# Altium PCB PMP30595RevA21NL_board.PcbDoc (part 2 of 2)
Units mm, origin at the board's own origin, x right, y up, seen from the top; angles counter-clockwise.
Board outline 110.49 x 76.2 mm, 2 copper layers (Top Layer, Bottom Layer), stack 1.575 mm thick; 77 components, 38 nets, 187 pads, 95 vias.
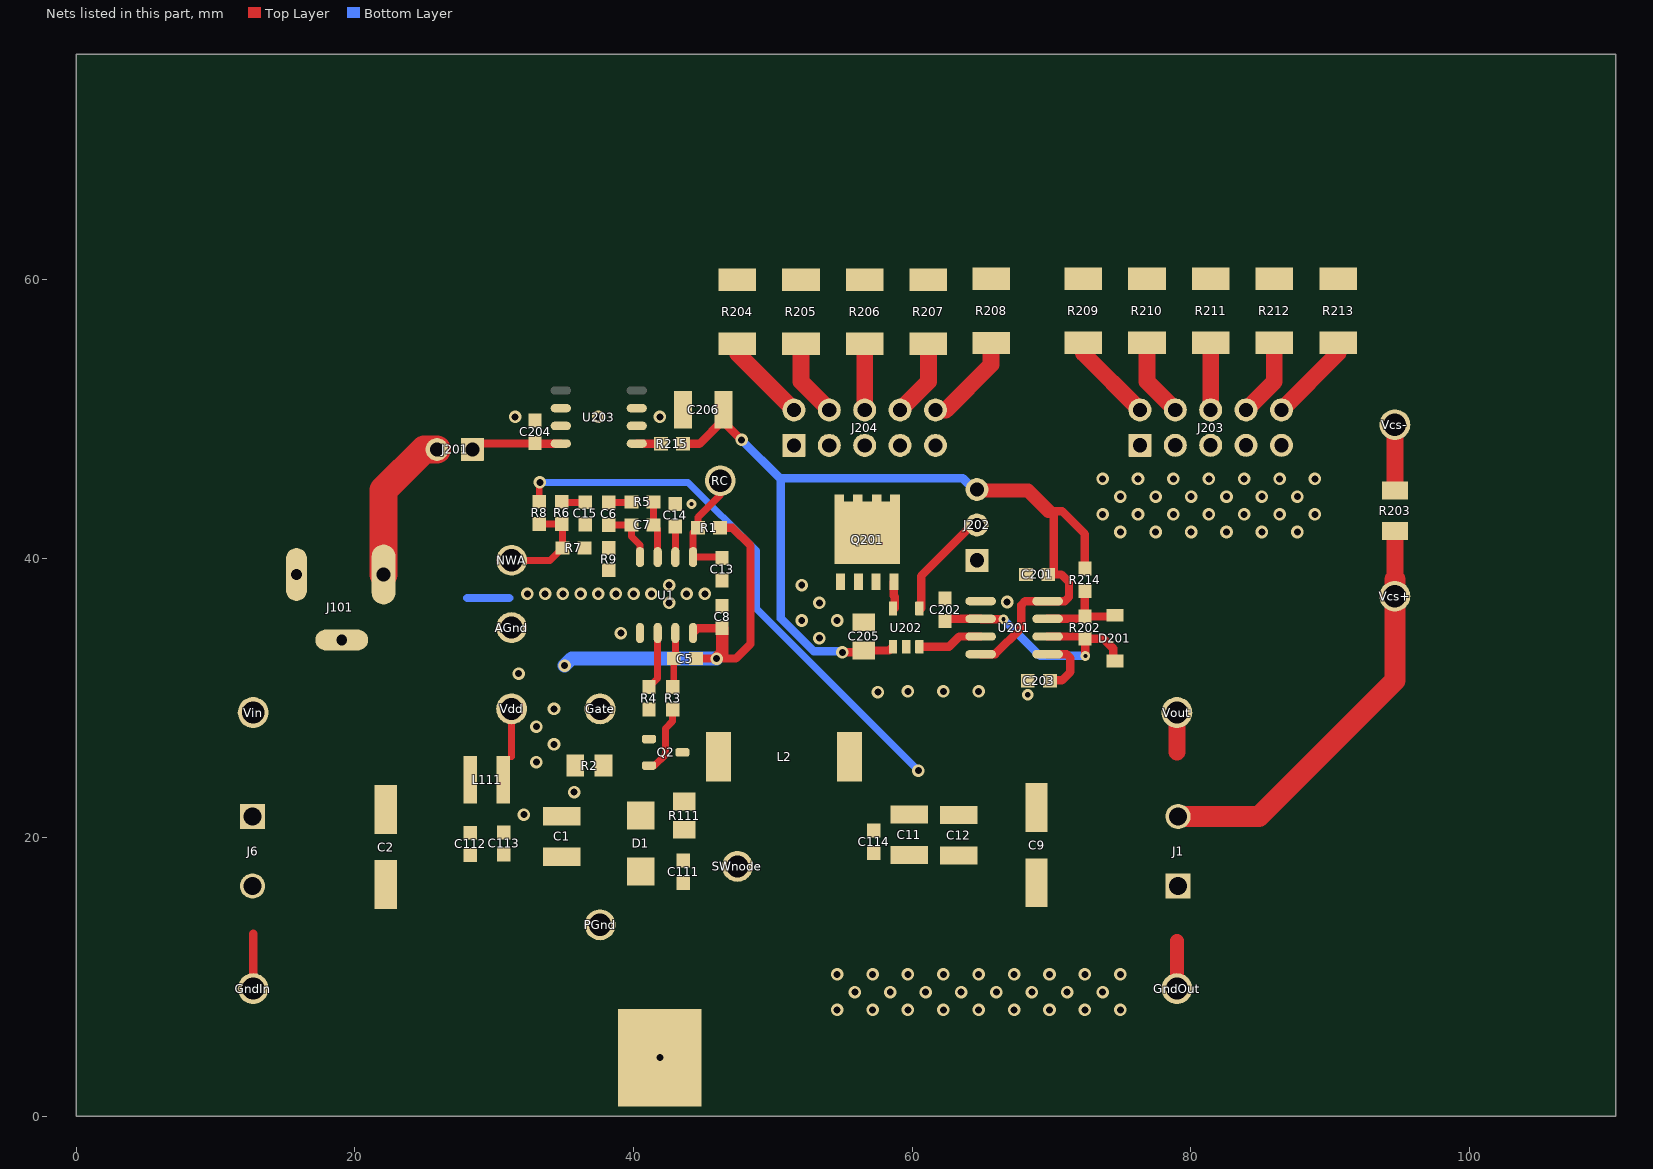
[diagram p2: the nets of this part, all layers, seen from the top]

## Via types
v1: diameter 0.9, hole 0.5, Top Layer to Bottom Layer, 81 vias
v2: diameter 0.9, hole 0.5, Top Layer to Bottom Layer, tented top, 10 vias
v3: diameter 0.7, hole 0.3, Top Layer to Bottom Layer, 2 vias
v4: diameter 0.7, hole 0.3, Top Layer to Bottom Layer, tented top, 1 vias
v5: diameter 0.8, hole 0.4, Top Layer to Bottom Layer, tented top, 1 vias

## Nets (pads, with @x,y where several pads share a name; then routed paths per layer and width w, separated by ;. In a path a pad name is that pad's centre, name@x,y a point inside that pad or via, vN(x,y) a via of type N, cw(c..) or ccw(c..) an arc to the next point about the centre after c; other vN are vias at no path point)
5V0: C9.1 C11.1 C12.1 C114.1 J1.2 L2.2 R8.1 R203.1 Vcs+.1 Vout.1 | length 73.9
  Top Layer w0.5: R8.1@33.232,44.08 33.232,45.417 v1(33.282,45.466)
  Top Layer w1.2: 78.994,26.096 Vout.1@78.994,28.956 ; Vcs+.1@94.635,37.302 R203.1@94.635,41.984
  Top Layer w1.5: J1.2@79.079,21.502 84.875,21.502 94.635,31.262 94.635,38.492
  Bottom Layer w0.5: v1(33.282,45.466) 43.92,45.466 48.813,40.573 48.813,36.404 v1(60.439,24.778)
12V0: C2.1 C112.1 J6.1 J101.1 J201.2 L111.1 Vin.1 | length 11.1
  Top Layer w2: J101.1@22.056,38.862 22.056,44.916 24.975,47.835 J201.2@25.894,47.835
GND: AGnd.1 C1.2 C2.2 C8.2 C9.2 C11.2 C12.2 C13.2 C14.2 C111.2 C112.2 C113.2 C114.2 C201.2 C202.2 C203.2 C204.2 C205.2 C206.2 D1.2 GndIn.1 GndOut.1 J1.1 J6.2 J101.2 J101.3 J202.1 J203.1 J203.3 J203.5 J203.7 J203.9 pad.1 PGnd.1 Q201.1 Q201.2 Q201.3 R9.1 U1.5 U201.1 U202.2 U203.2 U203.3 U203.6 U203.7 | length 10.4
  Top Layer w0.6: GndIn.1@12.7,9.144 12.7,13.081
  Top Layer w1: GndOut.1@78.994,9.144 78.994,12.573
  Bottom Layer w0.6: 28.067,37.172 31.076,37.172
  other v1: 54.61,7.62 57.15,7.62 59.69,7.62 62.23,7.62 64.77,7.62 67.31,7.62 69.85,7.62 72.39,7.62 74.93,7.62 55.88,8.89 58.42,8.89 60.96,8.89 63.5,8.89 66.04,8.89 68.58,8.89 71.12,8.89 73.66,8.89 54.61,10.16 57.15,10.16 59.69,10.16 62.23,10.16 64.77,10.16 67.31,10.16 69.85,10.16 72.39,10.16 74.93,10.16 57.531,30.42 59.69,30.48 62.23,30.48 64.77,30.48 53.34,34.29 39.09,34.66 52.07,35.56 54.61,35.56 53.34,36.83 32.385,37.465 33.655,37.465 34.925,37.465 36.195,37.465 37.465,37.465 38.735,37.465 52.07,38.1 74.93,41.91 77.47,41.91 80.01,41.91 82.55,41.91 85.09,41.91 87.63,41.91 73.66,43.18 76.2,43.18 78.74,43.18 81.28,43.18 83.82,43.18 86.36,43.18 88.9,43.18 74.93,44.45 77.47,44.45 80.01,44.45 82.55,44.45 85.09,44.45 87.63,44.45 73.66,45.72 76.2,45.72 78.74,45.72 81.28,45.72 83.82,45.72 86.36,45.72 88.9,45.72 31.496,50.165 37.465,50.165 41.893,50.165
  other v2: 42.545,36.83 66.802,36.885 40.005,37.465 41.275,37.465 43.815,37.465 45.113,37.465 42.545,38.1
  other v3: 44.159,43.916
  other v5: 68.288,30.226
NetC1_1: C1.1 C5.1 C8.1 C113.1 L111.2 R1.2 R2.1 U1.8 Vdd.1 | length 33.5
  Top Layer w0.5: 31.242,25.781 Vdd.1@31.242,29.21 ; C5.1@44.268,33.043 C5.1@44.484,32.827
  Top Layer w0.6: U1.8@44.268,34.66 44.622,35.014 C8.1@46.355,35.014 ; C5.1@44.484,32.827 v2(45.959,32.827) 47.337,32.827 48.387,33.877 48.387,40.927 47.103,42.211 R1.2@46.211,42.211
  Top Layer w0.9: v2(45.959,32.827) 46.355,33.223 C8.1@46.355,35.014
  Bottom Layer w1: v1(35.052,32.317) 35.562,32.827 v2(45.959,32.827)
  other v1: 32.131,21.625 35.73,23.247 33.02,25.4 34.29,26.67 33.02,27.94 34.29,29.21 31.75,31.75
NetC5_2: C5.2 R3.1 U1.7 | length 4
  Top Layer w0.5: R3.1@42.806,30.772 42.884,30.849 C5.2@42.884,32.827 42.998,32.941 U1.7@42.998,34.66
NetC6_1: C6.1 C7.1 C15.2 R7.2 R9.2 U1.4 | length 4.2
  Top Layer w0.5: C6.1@38.227,42.418 C7.1@39.84,42.418 39.84,41.592 40.458,40.973 U1.4@40.458,40.11
NetC6_2: C6.2 R5.2 | length 1.6
  Top Layer w0.5: C6.2@38.227,44.018 39.789,44.018 R5.2@39.84,44.069
NetC7_2: C7.2 R5.1 U1.3 | length 4.1
  Top Layer w0.5: R5.1@41.44,44.069 C7.2@41.44,42.418 41.728,42.13 U1.3@41.728,40.11
NetC13_1: C13.1 R1.1 RC.1 U1.1 | length 8.4
  Top Layer w0.5: RC.1@46.228,45.593 46.228,44.585 44.611,42.968 R1.1@44.611,42.211 44.268,41.868 U1.1@44.268,40.11 46.288,40.11 C13.1@46.355,40.043
NetC14_1: C14.1 U1.2 | length 2.2
  Top Layer w0.5: U1.2@42.998,40.11 C14.1@42.998,42.316
NetC15_1: C15.1 R6.1 | length 1.7
  Top Layer w0.5: R6.1@34.85,44.08 34.887,44.043 C15.1@36.534,44.043
NetC111_1: C111.1 R111.1
NetC201_1: C201.1 C205.1 C206.1 J202.3 R214.2 R215.2 U201.4 U201.8 U202.1 | length 72.3
  Top Layer w0.6: R215.2@43.556,48.235 44.718,48.235 C206.1@46.447,49.964 ; C206.1@46.447,50.673 C206.1@46.447,49.964 ; v2(47.752,48.514) 46.447,49.819 C206.1@46.447,49.964 ; v2(54.991,33.274) 56.388,33.274 C205.1@56.515,33.401 58.337,33.401 U202.1@58.613,33.677 ; U201.4@64.91,33.139 65.948,33.139 67.826,35.017 67.826,36.672 68.103,36.949 U201.8@69.71,36.949 70.949,36.949 71.247,37.247 71.247,38.312 70.697,38.862 C201.1@69.761,38.862 70.157,39.258 70.157,43.021 69.776,43.402 70.744,43.402 72.39,41.755 R214.2@72.39,39.281 ; C201.1@69.776,38.681 C201.1@69.863,38.768
  Top Layer w1: J202.3@64.516,44.873 68.305,44.873 69.776,43.402
  Bottom Layer w0.6: v2(47.752,48.514) 50.501,45.765 ; v2(54.991,33.274) 54.925,33.34 52.938,33.34 50.572,35.706 50.572,45.694 50.501,45.765 ; J202.3@64.516,44.873 63.624,45.765 50.501,45.765
NetC202_1: C202.1 D201.1 R202.1 U201.2 U201.6 | length 18.3
  Top Layer w0.6: C202.1@62.484,35.514 62.649,35.679 U201.2@64.91,35.679 64.943,35.646 v4(66.548,35.646) ; U201.6@69.71,34.409 72.229,34.409 R202.1@72.39,34.248 ; v3(72.423,33.02) 72.423,34.215 R202.1@72.39,34.248 ; D201.1@74.422,32.644 74.422,33.546 73.72,34.248 R202.1@72.39,34.248
  Bottom Layer w0.6: v4(66.548,35.646) 69.174,33.02 v3(72.423,33.02)
NetC203_1: C203.1 U201.5 | length 4.5
  Top Layer w0.6: U201.5@69.71,33.139 71.068,33.139 71.348,32.859 71.348,31.877 70.733,31.262 69.916,31.262 C203.1@69.888,31.234
NetC204_1: C204.1 J201.1 U203.8 | length 6.9
  Top Layer w0.6: J201.1@27.94,48.26 32.881,48.26 C204.1@32.931,48.31 32.987,48.254 U203.8@34.778,48.254
NetD1_1: D1.1 L2.1 Q2.3 R111.2 SWnode.1
NetD201_2: D201.2 R202.2 R214.1 U201.7 | length 6.6
  Top Layer w0.6: U201.7@69.71,35.679 72.221,35.679 R202.2@72.39,35.848 ; R214.1@72.39,37.681 R202.2@72.39,35.848 ; D201.2@74.422,35.919 74.35,35.848 R202.2@72.39,35.848
NetGate_1: Gate.1 Q2.1 R4.2
NetJ202_2: J202.2 U202.4 | length 7.7
  Top Layer w0.6: U202.4@60.64,36.427 60.64,38.742 64.231,42.333 J202.2@64.516,42.333
NetJ203_2: J203.2 R209.1 | length 6.5
  Top Layer w1.2: R209.1@72.27,55.485 72.27,54.737 J203.2@76.334,50.673
NetJ203_4: J203.4 R210.1 | length 5.7
  Top Layer w1.2: R210.1@76.842,55.485 76.842,52.705 J203.4@78.874,50.673
NetJ203_6: J203.6 R211.1 | length 4.8
  Top Layer w1.2: J203.6@81.414,50.673 R211.1@81.414,55.485
NetJ203_8: J203.8 R212.1 | length 5.7
  Top Layer w1.2: J203.8@83.954,50.673 85.986,52.705 R212.1@85.986,55.485
NetJ203_10: J203.10 R213.1 | length 6.5
  Top Layer w1.2: J203.10@86.494,50.673 90.558,54.737 R213.1@90.558,55.485
NetJ204_1: J204.1 J204.3 J204.5 J204.7 J204.9 Q201.5 Q201.6 Q201.7 Q201.8 Q201.9
NetJ204_2: J204.2 R204.1 | length 6.4
  Top Layer w1.2: R204.1@47.442,55.423 47.442,54.731 J204.2@51.506,50.667
NetJ204_4: J204.4 R205.1 | length 5.6
  Top Layer w1.2: R205.1@52.014,55.423 52.014,52.699 J204.4@54.046,50.667
NetJ204_6: J204.6 R206.1 | length 4.8
  Top Layer w1.2: J204.6@56.586,50.667 R206.1@56.586,55.423
NetJ204_8: J204.8 R207.1 | length 5.6
  Top Layer w1.2: J204.8@59.126,50.667 61.158,52.699 R207.1@61.158,55.423
NetJ204_10: J204.10 R208.1 | length 6.9
  Top Layer w1.2: J204.10@61.666,50.667 62.411,50.667 65.656,53.912 R208.1@65.656,55.479
NetNWA_1: NWA.1 R6.2 R7.1 R8.2 | length 7.4
  Top Layer w0.5: NWA.1@31.242,39.878 33.998,39.878 R7.1@34.887,40.767 34.887,42.443 R6.2@34.85,42.48 R8.2@33.232,42.48
NetQ2_2: Q2.2 R2.2 R3.2 | length 5
  Top Layer w0.5: Q2.2@41.106,25.146 41.511,25.146 42.291,25.926 42.291,27.813 42.806,28.328 R3.2@42.806,29.172
NetQ201_4: Q201.4 U202.5 | length 1.9
  Top Layer w0.6: Q201.4@58.674,38.346 58.674,37.338 58.74,37.272 U202.5@58.74,36.427
NetR4_1: R4.1 U1.6 | length 4.1
  Top Layer w0.5: R4.1@41.106,30.772 41.728,31.394 U1.6@41.728,34.66
NetR203_2: R203.2 R204.2 R205.2 R206.2 R207.2 R208.2 R209.2 R210.2 R211.2 R212.2 R213.2 Vcs-.1 | length 4.7
  Top Layer w1.2: R203.2@94.635,44.884 Vcs-.1@94.635,49.61
NetR215_1: R215.1 U203.1 | length 1.7
  Top Layer w0.6: U203.1@40.228,48.254 41.937,48.254 R215.1@41.956,48.235
NetU201_3: U201.3 U202.3 | length 4.4
  Top Layer w0.6: U202.3@60.767,33.677 62.641,33.677 63.373,34.409 U201.3@64.91,34.409
pads on no net: U203.4 U203.5

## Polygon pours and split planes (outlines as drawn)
NetC1_1 on Top Layer "TOP_LAYER_NETC1_1_P055" (solid, remove dead copper, pour order 55): 46.355,33.223 46.355,31.872 46.074,31.591 44.047,31.591 43.861,31.777 43.861,33.191 44.069,33.399 44.073,33.395 46.183,33.395
NetR215_1 on Top Layer "TOP_LAYER_NETR215_1_P051" (solid, remove dead copper, pour order 51): 37.93,48.437 38.203,48.71 42.418,48.71 42.418,47.112 42.164,46.857 38.227,46.863 37.93,47.16
NetC204_1 on Top Layer "TOP_LAYER_NETC204_1_P050" (solid, remove dead copper, pour order 50): 27.432,47.105 27.674,46.863 27.788,46.863 36.676,46.863 36.812,47 36.812,48.444 36.488,48.768 27.432,48.768
5V0 on Top Layer "TOP_LAYER_5V0_P048" (solid, remove dead copper, pour order 48): 79.479,24.13 84.328,24.13 92.837,32.639 92.837,36.667 93.472,37.302 95.816,37.302 96.413,36.705 96.413,30.881 85.675,20.143 79.479,20.143
GND on Top Layer "TOP_LAYER_GND_P040" (solid, remove dead copper, pour order 40): 40.416,51.181 44.028,51.181 44.268,50.941 44.268,49.491 43.888,49.11 43.871,49.127 40.803,49.127 29.946,49.127 29.718,49.355 29.718,50.941 29.958,51.181
GND on Top Layer "TOP_LAYER_GND_P032" (solid, remove dead copper, pour order 32): 50.69,41.744 53.267,39.167 60.677,39.167 63.881,42.371 63.881,47.371 65.786,49.276 88.519,49.276 90.424,47.371 90.424,32.206 87.64,29.422 55.918,29.422 50.69,34.65
NetJ204_1 on Top Layer "TOP_LAYER_NETJ204_1_P030" (solid, remove dead copper, pour order 30): 53.794,39.624 50.673,42.745 50.673,46.863 50.673,49.11 62.266,49.11 62.608,48.768 62.608,41.957 60.275,39.624
no net on Top Layer "TOP_LAYER_NONET_P028" (solid, remove dead copper, pour order 28): 47.879,50.11
NetR203_2 on Top Layer "TOP_LAYER_NETR203_2_P024" (solid, remove dead copper, pour order 24): 43.307,59.69 44.577,58.42 90.805,58.42 92.837,56.388 92.837,48.006 93.345,47.498 96.139,47.498 97.282,48.641 97.282,69.025 94.044,72.263 44.718,72.263 44.397,72.21 43.307,71.12
NetC6_1 on Top Layer "TOP_LAYER_NETC6_1_P022" (solid, remove dead copper, pour order 22): 38.735,40.25 38.735,42.926 35.883,42.926 35.883,40.259
GND on Top Layer "TOP_LAYER_GND_P018" (solid, remove dead copper, pour order 18): 30.217,33.782 30.217,44.314 31.75,45.847 47.394,45.847 48.895,44.346 48.895,33.782
NetC111_1 on Top Layer "TOP_LAYER_NETC111_1_P002" (solid, remove dead copper, pour order 2): 44.484,17.793 44.484,21.209 42.757,21.209 42.757,17.793
5V0 on Top Layer "TOP_LAYER_5V0_P010" (solid, remove dead copper, pour order 10): 54.619,19.939 54.619,28.263 81.534,28.263 81.534,20.066
NetGate_1 on Top Layer "TOP_LAYER_NETGATE_1_P009" (solid, remove dead copper, pour order 9): 38.532,26.543 cw(c38.532,29.083) 35.992,29.083 35.992,29.213 cw(c37.551,29.213) 37.551,30.772 38.778,30.772 cw(c38.778,30.146) 39.22,30.589 39.71,30.099 ccw(c40.323,30.712) 40.323,29.845 41.474,29.845 cw(c41.474,29.591) 41.728,29.591 41.728,26.869 cw(c41.402,26.869) 41.402,26.543
NetD1_1 on Top Layer "TOP_LAYER_NETD1_1_P000" (solid, remove dead copper, pour order 0): 48.641,17.925 cw(c47.442,17.925) 47.442,16.726 cw(c47.442,17.94) 46.228,17.94 46.228,20.792 ccw(c45.466,20.792) 45.466,21.554 45.047,21.554 cw(c45.047,21.643) 44.958,21.643 44.958,24.092 cw(c45.212,24.092) 45.212,24.346 48.641,24.257
NetD1_1 on Top Layer "TOP_LAYER_NETD1_1_P008" (solid, remove dead copper, pour order 8): 41.414,20.108 ccw(c41.414,20.828) 42.134,20.828 cw(c42.864,20.828) 42.864,21.558 46.482,21.558 ccw(c46.482,23.717) 48.641,23.717 48.641,27.94 ccw(c48.26,27.94) 48.26,28.321 44.015,28.321 ccw(c44.015,27.288) 42.981,27.288 42.981,24.964 cw(c41.084,24.964) 42.426,23.622 cw(c41.506,24.542) 41.506,23.241 39.718,23.241 ccw(c39.718,22.131) 38.608,22.131 38.608,20.87 ccw(c39.37,20.87) 39.37,20.108
NetQ2_2 on Top Layer "TOP_LAYER_NETQ2_2_P007" (solid, remove dead copper, pour order 7): 37.211,23.622 41.681,23.622 41.681,26.296 37.211,26.296
NetC1_1 on Top Layer "TOP_LAYER_NETC1_1_P006" (solid, remove dead copper, pour order 6): 36.572,26.641 35.433,27.78 35.205,28.008 35.212,28.311 35.212,30.33 36.505,31.623 39.983,31.623 40.505,32.145 40.505,33.308 40.386,33.427 30.882,33.427 29.967,32.512 29.972,19.812 36.572,19.812
12V0 on Top Layer "TOP_LAYER_12V0_P005" (solid, remove dead copper, pour order 5): 10.158,19.812 28.956,19.812 28.956,43.434 10.159,43.434
GND on Top Layer "TOP_LAYER_GND_P003" (solid, remove dead copper, pour order 3): 10.159,19.304 10.159,3.81 81.534,3.81 81.534,19.304
NetC1_1 on Bottom Layer "BOTTOM_LAYER_NETC1_1_P053" (solid, remove dead copper, pour order 53): 46.183,33.395 46.355,33.223 46.355,31.872 46.074,31.591 36.505,31.591 35.212,30.298 35.212,28.279 35.205,27.976 36.572,26.609 36.572,19.78 29.972,19.78 29.967,32.48 30.882,33.395
no net on Bottom Layer "BOTTOM_LAYER_NONET_P046" (solid, remove dead copper, pour order 46): 52.451,32.639
GND on Bottom Layer "BOTTOM_LAYER_GND_P044" (solid, remove dead copper, pour order 44): 75.489,19.21 79.251,19.21 80.645,20.604 80.645,24.601 75.489,29.757 75.489,33.754 78.849,37.114 97.155,37.114 97.155,6.33 94.635,3.81 75.489,3.81
no net on Bottom Layer "BOTTOM_LAYER_NONET_P042" (solid, remove dead copper, pour order 42): 83.82,20.326
GND on Bottom Layer "BOTTOM_LAYER_GND_P038" (solid, remove dead copper, pour order 38): 57.321,22.657 57.321,22.168 53.848,18.694 58.74,18.693 81.14,18.693 97.155,34.708 97.155,69.215 93.98,72.39 44.484,72.39 44.46,72.39 43.19,71.119 43.19,49.334 46.932,49.334 50.292,45.974 50.292,36.066 57.321,29.037
GND on Bottom Layer "BOTTOM_LAYER_GND_P036" (solid, remove dead copper, pour order 36): 29.004,41.91 29.004,45.222 30.645,46.863 43.053,46.863 45.323,49.133 45.323,72.21 10.16,72.21 10.16,41.91
GND on Bottom Layer "BOTTOM_LAYER_GND_P034" (solid, remove dead copper, pour order 34): 81.534,3.81 10.158,3.81 10.16,43.434 28.956,43.434 29.004,43.386 29.004,19.304 81.534,19.304
GND on Bottom Layer "BOTTOM_LAYER_GND_P020" (solid, remove dead copper, pour order 20): 30.209,33.805 30.209,44.337 31.741,45.87 47.385,45.87 48.886,44.369 48.886,33.805

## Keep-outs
Keep-Out Layer:
  text ".Layer_Name" at 14.656,-21.806 h1.52

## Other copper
Top Layer:
  text ".Layer_Name" at 14.656,-21.806 h1.52
Bottom Layer:
  text ".Layer_Name" at 14.656,-21.806 h1.52

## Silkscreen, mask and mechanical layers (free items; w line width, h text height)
Top Overlay:
  lines w0.3: 18.415,27.94 18.415,12.7 32.131,12.7 ; 18.542,27.94 32.258,27.94 ; 33.274,27.94 34.544,27.94 ; 35.306,27.94 36.576,27.94 ; 37.338,27.94 38.608,27.94 ; 39.37,27.94 40.64,27.94 ; 41.402,27.94 42.672,27.94 ; 43.18,53.34 43.18,67.31 97.282,67.31 97.282,27.94 ; 44.397,53.34 44.45,53.34 ; 45.466,27.94 46.736,27.94 ; 47.498,27.94 48.768,27.94 ; 49.403,27.94 73.152,27.94 ; 49.53,27.94 49.53,46.355 ; 97.319,27.94 73.152,27.94 ; 32.131,12.7 73.115,12.7 73.152,27.94 ; 32.131,12.7 32.131,26.846 32.131,46.355 ; 32.131,46.355 32.131,53.34 49.53,53.34 49.53,46.355 ; 32.131,46.355 49.53,46.355
  text "Onboard Load" at 62.936,67.945 h1
  text "LDO 8V" at 34.544,53.848 h1
  text "Bias" at 25.146,44.884 h1
  text "Off" at 66.373,44.544 h1
  text "On" at 66.373,39.878 h1
  text "*Ctrl*" at 33.006,35.052 h1.5
  text "*Power Stage*" at 57.912,25.654 h1.5
  text "VM Buck Converter" at 44.45,10.795 h1
  text "Input Filter / w/ Bulk Cap" at 17.145,7.62 h1
  text "'.PRJ_Number'A21 (= PMP7154 \"reLOADed\")" at 3.937,1.778 h2
  text "12/2018" at 103.124,0.889 h1
  text ".Layer_Name" at 14.656,-21.806 h1.52
Bottom Overlay:
  text ".Layer_Name" at 14.656,-21.806 h1.52
Top Paste:
  text ".Layer_Name" at 14.656,-21.806 h1.52
Bottom Paste:
  text ".Layer_Name" at 14.656,-21.806 h1.52
Top Solder:
  text ".Layer_Name" at 14.656,-21.806 h1.52
  text ".Layer_Name" at 14.656,-21.806 h1.52
Bottom Solder:
  text "'.PRJ_Number'A21" at 92.158,68.58 h2
  text ".Layer_Name" at 14.656,-21.806 h1.52
Drill Guide:
  text ".Layer_Name" at 14.656,-21.806 h1.52
M1 Board Outline:
  the board outline again, w0.254
  text ".Layer_Name" at 14.656,-21.806 h1.52
M2 Board Dimensions:
  rectangle: 0,-6.985 3.175,-3.81
  rectangle: 3.175,-10.16 12.7,-6.985
  lines w0.178: 0,-6.985 25.4,-6.985 ; 3.175,-10.16 3.175,-3.81 ; 6.35,-10.16 6.35,-3.81 ; 12.7,-10.16 12.7,-3.81 ; 19.05,-10.16 19.05,-3.81 ; 0,-10.16 25.4,-10.16 25.4,-3.81 0,-3.81 0,-10.16
  text "'.Print_Date' '.Print_Time'" at 1.524,77.724 h1.85
  text ".Layer_Name" at 14.656,-21.806 h1.52
M3 3D STEP Top:
  text ".Layer_Name" at 14.656,-21.806 h1.52
M4 3D STEP Bottom:
  text ".Layer_Name" at 14.656,-21.806 h1.52
M5 Assembly Top:
  lines w0.254: -7.417,-23.626 160.223,-23.626 ; -7.417,-18.462 160.274,-18.462 ; -7.417,-13.297 -7.417,-28.791 94.31,-28.791 160.274,-28.791 160.274,-13.297 -7.404,-13.297 -7.404,-28.791 32.614,-28.791 ; 55.194,-28.791 55.194,-13.297 ; 87.376,-18.462 87.376,-13.297 ; 108.712,-18.462 108.712,-13.297 ; 124.511,-28.956 124.511,-23.804
  text "COMPONENTS MARKED 'DNP' SHOULD NOT BE POPULATED." at 29.299,-8.09 h1.52
  text "ASSEMBLY VARIANT:" at 29.286,-11.024 h1.52
  text ".VariantName" at 55.601,-11.024 h1.52
  text "PCB VIEWED FROM TOP SIDE" at -5.804,-16.654 h1.52
  text "BOARD #:" at 57.099,-16.654 h1.52
  text ".PRJ_Number" at 70.955,-16.654 h1.52
  text "REV:" at 92.405,-16.654 h1.52
  text ".PCB_Rev" at 99.809,-16.654 h1.52
  text "SVN REV:" at 113.69,-16.654 h1.52
  text ".VersionControl_RevNumber" at 126.543,-16.654 h1.52
  text "TID #:" at 57.099,-21.819 h1.52
  text ".TID" at 70.955,-21.819 h1.52
  text "PLOT NAME =" at -5.804,-27.034 h1.52
  text ".plot_File_Name" at 14.656,-27.034 h1.52
  text "GENERATED    :" at 57.15,-27.034 h1.52
  text ".Print_Date" at 79.235,-27.034 h1.52
  text ".Print_Time" at 97.752,-27.034 h1.52
  text "TEXAS INSTRUMENTS" at 129.87,-27.034 h1.52
M6 Assembly Bottom:
  lines w0.254: -7.429,-18.474 160.261,-18.474 ; -7.379,-23.639 160.261,-23.639 ; 28.334,-28.969 28.334,-23.817 ; 44.133,-18.474 44.133,-13.31 ; 65.468,-18.474 65.468,-13.31 ; 97.65,-28.804 97.65,-13.31 ; 120.231,-28.804 160.249,-28.804 160.249,-13.31 -7.429,-13.31 -7.429,-28.804 58.534,-28.804 160.261,-28.804 160.261,-13.31
  text "COMPONENTS MARKED 'DNP' SHOULD NOT BE POPULATED." at 154.991,-8.077 h1.52
  text ".VariantName" at 128.473,-11.024 h1.52
  text "ASSEMBLY VARIANT:" at 154.864,-11.024 h1.52
  text ".VersionControl_RevNumber" at 26.302,-16.667 h1.52
  text "SVN REV:" at 39.154,-16.667 h1.52
  text ".PCB_Rev" at 53.035,-16.667 h1.52
  text "REV:" at 60.439,-16.667 h1.52
  text ".PRJ_Number" at 81.89,-16.667 h1.52
  text "BOARD #:" at 95.745,-16.667 h1.52
  text "PCB VIEWED FROM BOTTOM SIDE" at 158.648,-16.667 h1.52
  text ".TID" at 81.89,-21.831 h1.52
  text "TID #:" at 95.745,-21.831 h1.52
  text "TEXAS INSTRUMENTS" at 22.974,-27.047 h1.52
  text ".Print_Time" at 55.093,-27.047 h1.52
  text ".Print_Date" at 73.609,-27.047 h1.52
  text "GENERATED    :" at 95.694,-27.047 h1.52
  text ".plot_File_Name" at 138.189,-27.047 h1.52
  text "PLOT NAME =" at 158.648,-27.047 h1.52
M9 Title Sheet:
  drawing of 57 lines, arcs and shapes, not listed
  text "1" at 18.792,204.127 h1.78
  text "2" at 82.182,204.127 h1.78
  text "3" at 145.411,204.127 h1.78
  text "4" at 209.08,204.127 h1.78
  text "5" at 272.555,204.127 h1.78
  text "6" at 336.182,204.127 h1.78
  text "A" at -10.579,175.095 h1.78
  text "A" at 365.341,175.095 h1.78
  text "B" at -10.579,114.643 h1.78
  text "B" at 365.341,114.643 h1.78
  text "C" at -10.579,54.318 h1.78
  text "C" at 365.341,54.318 h1.78
  text "PROJECT TITLE:" at 288.125,7.048 h1.14
  text ".PRJ_Title" at 289.395,3.662 h1.78
  text "DESIGNED FOR:" at 288.125,-0.597 h1.14
  text ".PRJ_Customer" at 289.395,-4.153 h1.78
  text "D" at -10.579,-5.88 h1.78
  text "D" at 365.341,-5.88 h1.78
  text "FILE NAME:" at 288.125,-8.217 h1.14
  text ".PCB_File_Name_No_Path" at 289.395,-11.265 h1.78
  text "Texas Instruments (TI) and/or its licensors do not warrant the accuracy or completeness of this specification" at 161.9,-15.376 h1.14
  text "ENGINEER:" at 288.125,-15.583 h1.14
  text "LAYOUT BY:" at 326.352,-15.583 h1.14
  text "or any information contained therein. TI and/or its licensors do not warrant that this design will meet" at 160.757,-18.237 h1.14
  text ".PRJ_Engineer" at 289.395,-19.52 h1.78
  text ".PCB_Layout" at 327.635,-19.52 h1.78
  text "the specifications, will be suitable for your application or fit for any particular purpose, or will operate in" at 160.757,-21.099 h1.14
  text ".Layer_Name" at 14.656,-21.806 h1.52
  text "ALTIUM DESIGNER VERSION:" at 326.352,-23.457 h1.14
  text "an implementation. TI and/or its licensors do not warrant that the design is production worthy. You should" at 160.757,-23.961 h1.14
  text "completely validate and test your design implementation to confirm the system functionality for your application." at 161.9,-26.822 h1.14
  text ".print_Scale" at 289.395,-26.843 h1.78
  text ".Application_BuildNumber" at 327.635,-26.843 h1.78
  text "1" at 18.792,-32.093 h1.78
  text "2" at 82.182,-32.093 h1.78
  text "3" at 145.411,-32.093 h1.78
  text "4" at 209.08,-32.093 h1.78
  text "5" at 272.555,-32.093 h1.78
  text "6" at 336.182,-32.093 h1.78
M10 Fab Notes:
  drawing of 189 lines, arcs and shapes, not listed
  text "DESIGN INFORMATION" at 314.503,161.447 h1.52
  text "MIN. TRACK WIDTH:" at 298.131,158.091 h1.52
  text "8" at 325.976,158.091 h1.52
  text "MIL" at 329.907,158.091 h1.52
  text "MIN. CLEARANCE:" at 298.131,154.938 h1.52
  text "0.2" at 324.452,154.938 h1.52
  text "mm" at 329.907,154.938 h1.52
  text "MIN. VIA PAD SIZE:" at 298.131,151.785 h1.52
  text "24" at 325.214,151.785 h1.52
  text "MIL" at 329.907,151.785 h1.52
  text "0.05mm (2MIL)" at 315.784,148.486 h1.52
  text "MINIMUM ANNULAR RING" at 289.769,148.277 h1.52
  text "EXTERNAL" at 333.768,148.277 h1.52
  text "PER" at 294.849,145.48 h1.52
  text "IPC-D-275 CLASS 2 LEVEL C" at 300.437,145.48 h1.52
  text "MIL, HOLES" at 338.238,142.928 h1.52
  text "+/-" at 328.27,142.709 h1.52
  text "+/-" at 349.961,142.709 h1.52
  text "REGISTRATION TOLERANCES:" at 289.769,142.682 h1.52
  text "METAL" at 320.243,142.682 h1.52
  text "5" at 334.879,142.683 h1.52
  text "3" at 356.037,142.683 h1.52
  text "MIL" at 358.99,142.682 h1.52
  text "HOLE SIZE TOLERANCE (UNLESS OTHERWISE SPECIFIED):" at 289.769,140.185 h1.52
  text "+/-" at 349.961,140.112 h1.52
  text "3" at 356.037,140.085 h1.52
  text "MIL" at 358.99,140.085 h1.52
  text "MATERIAL:" at 287.87,136.589 h1.52
  text "FR-4 High Tg" at 312.926,133.324 h1.52
  text "X" at 309.257,133.122 h1.52
  text "FR-408" at 298.563,133.007 h1.52
  text "OTHER" at 336.358,133.007 h1.52
  text "62 MIL (1.6mm) +/-10%" at 306.694,129.374 h1.52
  text "X" at 303.643,129.312 h1.52
  text "THICKNESS:" at 289.769,129.165 h1.52
  text "OTHER" at 339.33,129.165 h1.52
  text "TOLERANCE:" at 289.769,125.652 h1.52
  text "X" at 311.314,125.652 h1.52
  text "ANSI IPC-6012 TYPE 3 CLASS 2" at 315.836,125.652 h1.52
  text "OTHER +/-" at 315.835,121.989 h1.52
  text "BOW & TWIST:" at 289.769,118.302 h1.52
  text "X" at 311.314,118.302 h1.52
  text "ANSI IPC-6012 TYPE 3 CLASS 2" at 315.836,118.302 h1.52
  text "OTHER +/-" at 315.835,114.576 h1.52
  text "DRILLING:" at 287.87,111.258 h1.52
  text "NC_DRILL FILES" at 332.599,108.586 h1.52
  text "REFERENCE:" at 289.769,108.486 h1.52
  text "X" at 306.463,108.484 h1.52
  text "AS SHOWN" at 310.984,108.486 h1.52
  text "X" at 329.348,108.486 h1.52
  text "OTHER" at 340.168,104.873 h1.52
  text "PTH COPPER THICKNESS:" at 289.761,104.783 h1.52
  text "X" at 318.697,104.783 h1.52
  text "20-30 um" at 321.948,104.783 h1.52
  text "BOARD FINISH:" at 287.87,101.034 h1.52
  text "SILKSCREEN:" at 291.812,98.237 h1.52
  text "X" at 316.14,98.237 h1.52
  text "TOP" at 319.112,98.237 h1.52
  text "X" at 329.094,98.237 h1.52
  text "BOTTOM" at 332.091,98.237 h1.52
  text "SILKSCREEN COLOR:" at 291.812,94.295 h1.52
  text "X" at 316.115,94.295 h1.52
  text "WHITE" at 319.112,94.295 h1.52
  text "OTHER" at 332.091,94.295 h1.52
  text "X" at 319.442,90.652 h1.52
  text "GREEN" at 322.439,90.652 h1.52
  text "OTHER" at 338.136,90.652 h1.52
  text "SOLDER RESIST COLOR:" at 291.812,90.477 h1.52
  text "X" at 319.442,86.734 h1.52
  text "MATTE" at 322.439,86.734 h1.52
  text "SEMI-GLOSS" at 338.125,86.717 h1.52
  text "IMMERSION GOLD (ENIG)" at 314.819,82.345 h1.52
  text "ENEPIG" at 348.793,82.162 h1.52
  text "SURFACE FINISH:" at 287.87,82.136 h1.52
  text "X" at 310.298,82.136 h1.52
  text "IMM. TIN/SILVER OR EQUIV" at 296.24,78.649 h1.52
  text "OTHER" at 332.599,78.549 h1.52
  text "ARRAY/PANEL:" at 287.87,74.602 h1.52
  text "CUT AND TRIM PER M1 BOARD OUTLINE" at 314.819,74.393 h1.52
  text "N.C. ROUTE" at 314.819,70.94 h1.52
  text "X" at 332.295,70.94 h1.52
  text "V. SCORE" at 336.816,70.94 h1.52
  text "CERTIFICATION:" at 287.87,67.66 h1.52
  text "MATERIALS AND WORKMANSHIP FOR ALL PCBS" at 306.285,67.66 h1.52
  text "TO MEET OR EXCEED THE REQUIREMENTS OF:" at 306.285,65.271 h1.52
  text "X" at 297.078,62.003 h1.52
  text "ANSI IPC-A-600F CLASS ->" at 300.329,62.003 h1.52
  text "X" at 342.188,62.003 h1.52
  text "2" at 344.982,62.003 h1.52
  text "1" at 336.981,61.965 h1.52
  text "3" at 353.973,61.965 h1.52
  text "X" at 317.702,58.252 h1.52
  text "RoHS" at 320.953,58.252 h1.52
  text "OTHER" at 337.321,58.252 h1.52
  text "PER ORDER" at 347.407,58.252 h1.52
  text "ALL BOARDS MUST MEET OR EXCEED UL94-V0 REQUIREMENTS." at 288.569,54.345 h1.52
  text "PCB MUST BEAR THE UL94V-0 UL REGISTERED MATERIAL ID NUMBER" at 288.569,51.397 h1.52
  text "ADDITIONAL REQUIREMENTS:" at 287.87,47.094 h1.52
  text "MICROSECTION:" at 289.769,44.373 h1.52
  text "YES" at 312.775,44.373 h1.52
  text "REQUIRED" at 334.657,40.707 h1.52
  text "BARE BOARD ELEC. TEST:" at 289.769,40.634 h1.52
  text "NONE" at 322.935,40.634 h1.52
  text "X" at 331.66,40.634 h1.52
  text "PER ORDER" at 349.693,40.634 h1.52
  text "XX MIL VIAS REQUIRE NON-CONDUCTIVE FILL AND PLANARIZE" at 294.04,35.428 h1.5
  text "XX MIL VIAS REQUIRE CONDUCTIVE FILL AND PLANARIZE" at 294.243,32.787 h1.52
  text "OUTER XX MIL TRACES REQUIRE 50 OHM SINGLE-ENDED IMPEDANCE" at 294.218,28.637 h1.47
  text "LAYER 2 & 3 (INNER LAYERS) XX MIL WIDE, XX MIL SPACE / TRACES REQUIRE 100 OHM DIFFERENTIAL IMPEDANCE" at 294.015,22.65 h1.52
  text ".Layer_Name" at 14.656,-21.806 h1.52
M11 Gerber Information:
  lines w0.254: -7.417,-23.626 160.223,-23.626 ; -7.417,-18.462 160.274,-18.462 ; -7.417,-13.297 -7.417,-28.791 94.31,-28.791 160.274,-28.791 160.274,-13.297 -7.404,-13.297 -7.404,-28.791 32.614,-28.791 ; 55.194,-28.791 55.194,-13.297 ; 87.376,-18.462 87.376,-13.297 ; 108.712,-18.462 108.712,-13.297 ; 124.511,-28.956 124.511,-23.804
  text "ALL ARTWORK VIEWED FROM TOP SIDE" at -5.804,-16.654 h1.52
  text "BOARD #:" at 57.099,-16.654 h1.52
  text ".PRJ_Number" at 70.955,-16.654 h1.52
  text "REV:" at 92.405,-16.654 h1.52
  text ".PCB_Rev" at 99.809,-16.654 h1.52
  text "SVN REV:" at 113.69,-16.654 h1.52
  text ".VersionControl_RevNumber" at 126.543,-16.654 h1.52
  text "LAYER NAME =" at -5.804,-21.806 h1.52
  text "TID #:" at 57.099,-21.819 h1.52
  text ".TID" at 70.955,-21.819 h1.52
  text "PLOT NAME =" at -5.804,-27.034 h1.52
  text ".plot_File_Name" at 14.656,-27.034 h1.52
  text "GENERATED    :" at 57.15,-27.034 h1.52
  text ".Print_Date" at 79.235,-27.034 h1.52
  text ".Print_Time" at 97.752,-27.034 h1.52
  text "TEXAS INSTRUMENTS" at 129.87,-27.034 h1.52
M12 Stackup:
  drawing of 191 lines, arcs and shapes, not listed
  text "Layer" at 248.865,188.023 h1.52
  text "Name" at 259.277,188.023 h1.52
  text "Material" at 282.892,188.023 h1.52
  text "Thickness" at 304.731,188.023 h1.52
  text "Constant" at 321.236,188.023 h1.52
  text "Board Layer Stack" at 335.711,188.023 h1.52
  text "1" at 248.865,184.975 h1.52
  text "Top Overlay" at 259.277,184.975 h1.52
  text "2" at 248.865,181.927 h1.52
  text "Top Solder" at 259.277,181.927 h1.52
  text "Solder Resist" at 282.892,181.927 h1.52
  text "0.40mil" at 304.731,181.927 h1.52
  text "3.5" at 321.236,181.927 h1.52
  text "3" at 248.865,178.879 h1.52
  text "Top Layer" at 259.277,178.879 h1.52
  text "Copper" at 282.892,178.879 h1.52
  text "1.40mil" at 304.731,178.879 h1.52
  text "4" at 248.865,175.832 h1.52
  text "Dielectric1" at 259.277,175.832 h1.52
  text "FR-4" at 282.892,175.832 h1.52
  text "59.20mil" at 304.731,175.832 h1.52
  text "4.8" at 321.236,175.832 h1.52
  text "5" at 248.865,172.784 h1.52
  text "Bottom Layer" at 259.277,172.784 h1.52
  text "Copper" at 282.892,172.784 h1.52
  text "1.40mil" at 304.731,172.784 h1.52
  text "6" at 248.865,169.736 h1.52
  text "Bottom Solder" at 259.277,169.736 h1.52
  text "Solder Resist" at 282.892,169.736 h1.52
  text "0.40mil" at 304.731,169.736 h1.52
  text "3.5" at 321.236,169.736 h1.52
  text "7" at 248.865,166.688 h1.52
  text "Bottom Overlay" at 259.277,166.688 h1.52
  text ".Layer_Name" at 14.656,-21.806 h1.52
M13 Component Bodies Top:
  text ".Layer_Name" at 14.656,-21.806 h1.52
M14 Component Bodies Bottom:
  text ".Layer_Name" at 14.656,-21.806 h1.52
M15 Courtyards Top:
  text ".Layer_Name" at 14.656,-21.806 h1.52
M16 Courtyards Bottom:
  text ".Layer_Name" at 14.656,-21.806 h1.52
Drill Drawing:
  circle w0.254: c136.241,72.096 r0.703
  lines w0.254: 135.538,65.42 135.89,65.42 136.241,65.068 136.593,65.42 136.944,65.42 136.593,65.771 136.944,66.123 136.593,66.123 136.241,66.474 135.89,66.123 135.538,66.123 135.89,65.771 135.538,65.42 ; 135.538,68.231 136.241,68.582 136.944,68.231 136.593,68.933 136.944,69.636 136.241,69.285 135.538,69.636 135.89,68.933 135.538,68.231 ; 135.538,74.555 136.944,74.555 136.944,75.961 135.538,75.961 135.538,74.555 ; 135.538,79.123 136.944,79.123 136.241,77.718 135.538,79.123 ; 135.538,81.231 135.89,81.231 135.89,80.88 136.593,80.88 136.593,81.231 136.944,81.231 136.944,81.934 136.593,81.934 136.593,82.285 135.89,82.285 135.89,81.934 135.538,81.934 135.538,81.231 ; 135.538,84.745 136.241,84.042 136.944,84.745 136.241,85.448 135.538,84.745 ; 135.538,87.205 135.538,87.556 135.89,87.907 135.538,88.259 135.538,88.61 135.89,88.61 136.241,88.259 136.593,88.61 136.944,88.61 136.944,88.259 136.593,87.907 136.944,87.556 136.944,87.205 136.593,87.205 136.241,87.556 135.89,87.205 135.538,87.205
  lines w0.305: 134.264,64.12 216.362,64.12 ; 134.264,89.418 216.362,89.418 ; 142.85,60.957 142.85,92.58 ; 151.287,60.957 151.287,92.58 ; 167.453,60.957 167.453,92.58 ; 174.037,60.957 174.037,92.58 ; 183.568,60.957 183.568,92.58 ; 201.972,60.957 201.972,92.58 ; 134.264,60.957 216.362,60.957 216.362,92.58 134.264,92.58 134.264,60.957
  text "Symbol" at 136.162,90.367 h1.83
  text "Quantity" at 143.799,90.367 h1.83
  text "Finished Hole Size" at 152.235,90.367 h1.83
  text "Plated" at 168.402,90.367 h1.83
  text "Hole Type" at 174.986,90.367 h1.83
  text "Drill Layer Pair" at 184.517,90.367 h1.83
  text "Hole Tolerance" at 202.92,90.367 h1.83
  text "3" at 143.799,87.205 h1.52
  text "11.81mil (0.300mm)" at 152.235,87.205 h1.52
  text "PTH" at 168.402,87.205 h1.52
  text "Round" at 174.986,87.205 h1.52
  text "Top Layer - Bottom Layer" at 184.517,87.205 h1.52
  text "1" at 143.799,84.042 h1.52
  text "15.75mil (0.400mm)" at 152.235,84.042 h1.52
  text "PTH" at 168.402,84.042 h1.52
  text "Round" at 174.986,84.042 h1.52
  text "Top Layer - Bottom Layer" at 184.517,84.042 h1.52
  text "92" at 143.799,80.88 h1.52
  text "19.69mil (0.500mm)" at 152.235,80.88 h1.52
  text "PTH" at 168.402,80.88 h1.52
  text "Round" at 174.986,80.88 h1.52
  text "Top Layer - Bottom Layer" at 184.517,80.88 h1.52
  text "25" at 143.799,77.718 h1.52
  text "40.00mil (1.016mm)" at 152.235,77.718 h1.52
  text "PTH" at 168.402,77.718 h1.52
  text "Round" at 174.986,77.718 h1.52
  text "Top Layer - Bottom Layer" at 184.517,77.718 h1.52
  text "4" at 143.799,74.555 h1.52
  text "51.18mil (1.300mm)" at 152.235,74.555 h1.52
  text "PTH" at 168.402,74.555 h1.52
  text "Round" at 174.986,74.555 h1.52
  text "Top Layer - Bottom Layer" at 184.517,74.555 h1.52
  text "13" at 143.799,71.393 h1.52
  text "63.00mil (1.600mm)" at 152.235,71.393 h1.52
  text "PTH" at 168.402,71.393 h1.52
  text "Round" at 174.986,71.393 h1.52
  text "Top Layer - Bottom Layer" at 184.517,71.393 h1.52
  text "2" at 143.799,68.231 h1.52
  text "29.92mil (0.760mm)" at 152.235,68.231 h1.52
  text "PTH" at 168.402,68.231 h1.52
  text "Slot" at 174.986,68.231 h1.52
  text "Top Layer - Bottom Layer" at 184.517,68.231 h1.52
  text "1" at 143.799,65.068 h1.52
  text "39.76mil (1.010mm)" at 152.235,65.068 h1.52
  text "PTH" at 168.402,65.068 h1.52
  text "Slot" at 174.986,65.068 h1.52
  text "Top Layer - Bottom Layer" at 184.517,65.068 h1.52
  text "141 Total" at 143.799,61.906 h1.52
  text "Slot definitions :" at 136.162,59.693 h1.52
  text "Routed Path Length" at 147.608,59.693 h1.52
  text "= Calculated from tool start centre position to tool end centre position." at 161.32,59.693 h1.52
  text "Hole Length" at 147.608,58.428 h1.52
  text "= Routed Path Length + Tool Size = Slot length as defined in the PCB layout" at 156.244,58.428 h1.52
  text ".Layer_Name" at 14.656,-21.806 h1.52
M17 Embedded Cavity:
  text ".Layer_Name" at 14.656,-21.806 h1.52
M18 Embedded Assembly:
  text ".Layer_Name" at 14.656,-21.806 h1.52
M19 Embedded Keepout:
  text ".Layer_Name" at 14.656,-21.806 h1.52

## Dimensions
0,0 to 0,76.2 on M2 Board Dimensions
0,0 to 110.49,0 on M2 Board Dimensions
0,-10.16 to 25.4,-10.16 on M2 Board Dimensions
